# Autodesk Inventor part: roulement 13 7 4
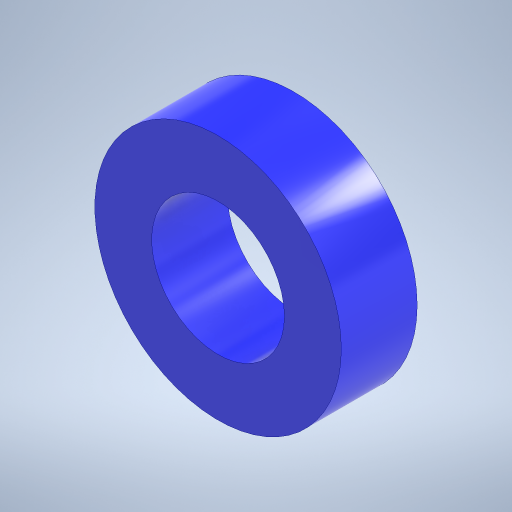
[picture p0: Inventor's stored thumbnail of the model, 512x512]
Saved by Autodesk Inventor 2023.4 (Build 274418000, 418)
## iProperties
Created: 2025-06
Part Number: roulement 13 7 4
Material: Générique
Document SubType Name: Modeling
Designer: mel
Density: 1 g/cm^3
Appearance: Bleu - Peinture murale - Brillant
Author: mel
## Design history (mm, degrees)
sketch "Esquisse1"
  geometry: C1 r 6.5 at (0, 0); C2 r 3.5 at (0, 0); 1 further point
  constraints: 2 centre point, 2 coincident
  dimensions: "d0" = 13 diameter of C1; "d1" = 7 diameter of C2
extrude "Extrusion1" new body sketch "Esquisse1" distance "d2" = 4; taper "d3" = 0 deg
node "Solide1"
